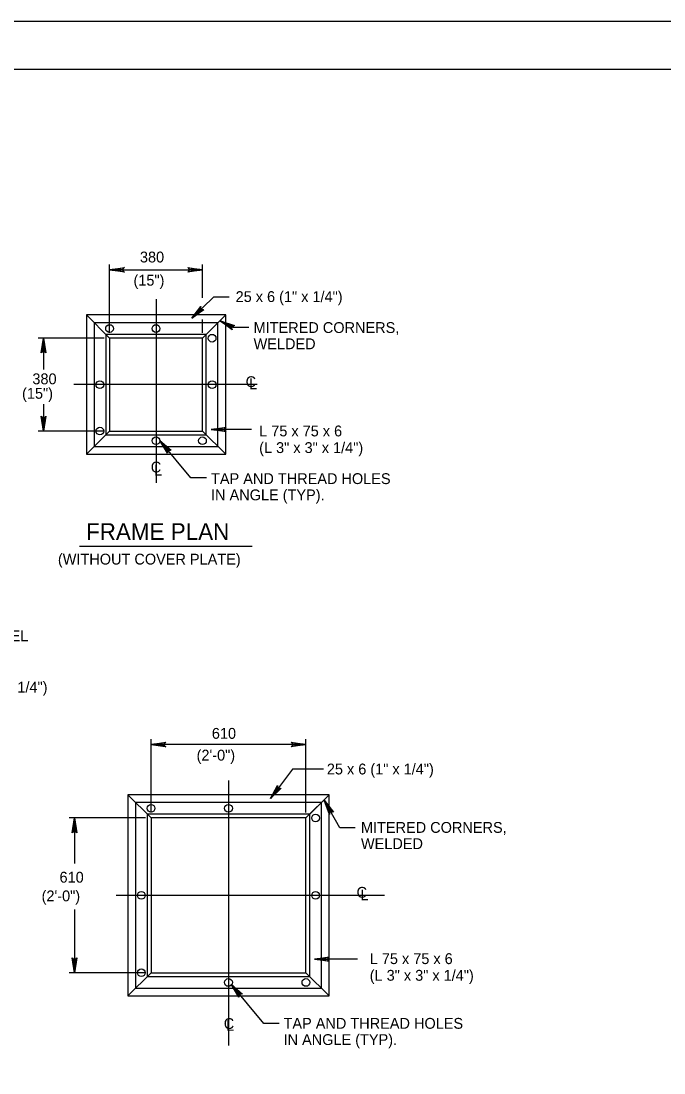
# Model space of a CAD drawing. Extents: x 638447 to 639352, y 298406 to 299000.
# Drawn here: x 638838.1 to 639037.5, y 298674.3 to 299000.5 of the extents above; entities that cross this region are included whole.
import ezdxf

# ---------------------------------------------------------------- set-up
doc = ezdxf.new("R2010")
doc.units = 0
for name, color, linetype in [('1', 7, 'Continuous'), ('2', 7, 'Continuous'), ('3', 7, 'Continuous'), ('PLT-BNDY', 7, 'Continuous')]:
    doc.layers.add(name, color=color, linetype=linetype)

msp = doc.modelspace()

# ---------------------------------------------------------------- linework, layer by layer
at = {"layer": '1'}
msp.add_lwpolyline([(639272.394625, 298421.4725), (639272.394625, 298985.4725), (638486.394625, 298985.4725), (638486.394625, 298421.4725), (639272.394625, 298421.4725), (639272.394625, 298447.8315), (639072.394625, 298447.8315), (639072.394625, 298512.509), (639272.394625, 298512.509), (639272.394625, 298541.4725), (639072.394625, 298541.4725), (639072.394625, 298421.4725), (639151.196125, 298421.4725), (639151.196125, 298447.8315), (639151.196125, 298421.4725), (639228.196125, 298421.4725), (639228.196125, 298447.8315), (639228.196125, 298435.515), (639272.394625, 298435.515)], dxfattribs=at)
at = {"layer": '2'}
for p, q in [((638865.586375, 298903.796), (638865.586375, 298925.002)), ((638894.386375, 298914.64725), (638894.386375, 298925.002)), ((638865.586375, 298923.322), (638894.386375, 298923.322)), ((638879.986375, 298914.196), (638879.986375, 298857.294)), ((638865.586375, 298902.116), (638858.386375, 298909.316)), ((638894.386375, 298902.116), (638901.586375, 298909.316)), ((638879.986375, 298905.116), (638879.986375, 298905.116)), ((638894.386375, 298903.796), (638894.386375, 298907.89375)), ((638863.906375, 298902.116), (638843.452375, 298902.116)), ((638845.132375, 298902.116), (638845.132375, 298892.43875)), ((638911.330375, 298887.716), (638854.500375, 298887.716)), ((638862.586375, 298887.716), (638862.586375, 298887.716)), ((638897.386375, 298887.716), (638897.386375, 298887.716)), ((638845.132375, 298881.65925), (638845.132375, 298873.316)), ((638863.906375, 298873.316), (638843.452375, 298873.316)), ((638858.386375, 298866.116), (638865.586375, 298873.316)), ((638901.586375, 298866.116), (638894.386375, 298873.316)), ((638879.986375, 298870.316), (638879.986375, 298870.316)), ((638878.458375, 298755.024), (638878.458375, 298777.77)), ((638926.458375, 298755.024), (638926.458375, 298777.77)), ((638926.458375, 298776.09), (638878.458375, 298776.09)), ((638902.458375, 298764.956), (638902.458375, 298682.822)), ((638878.458375, 298753.344), (638871.258375, 298760.544)), ((638926.458375, 298753.344), (638933.658375, 298760.544)), ((638927.658375, 298754.544), (638931.258375, 298758.144)), ((638876.778375, 298753.344), (638853.014375, 298753.344)), ((638854.694375, 298753.344), (638854.694375, 298739.25225)), ((638950.806375, 298729.344), (638867.594375, 298729.344)), ((638854.694375, 298724.96625), (638854.694375, 298705.344)), ((638876.778375, 298705.344), (638853.014375, 298705.344)), ((638871.258375, 298698.144), (638878.458375, 298705.344)), ((638933.658375, 298698.144), (638926.458375, 298705.344))]:
    msp.add_line(p, q, dxfattribs=at)
for points in [[(638869.944375, 298922.776), (638869.782375, 298923.092), (638865.586375, 298923.322), (638869.944375, 298922.776), (638870.168375, 298922.584), (638865.586375, 298923.322), (638869.780375, 298923.53), (638869.932375, 298923.842), (638865.586375, 298923.322), (638870.168375, 298924.052), (638869.932375, 298923.842)], [(638890.026375, 298923.87), (638890.190375, 298923.554), (638894.386375, 298923.322), (638890.026375, 298923.87), (638889.804375, 298924.062), (638894.386375, 298923.322), (638890.192375, 298923.116), (638890.040375, 298922.804), (638894.386375, 298923.322), (638889.804375, 298922.594), (638890.040375, 298922.804)], [(638902.660375, 298914.86), (638897.860375, 298914.86), (638891.046375, 298908.296)], [(638894.566375, 298910.926), (638894.230375, 298911.04), (638891.046375, 298908.296), (638894.566375, 298910.926), (638894.860375, 298910.944), (638891.046375, 298908.296), (638893.922375, 298911.354), (638893.816375, 298911.686), (638891.046375, 298908.296), (638893.842375, 298912), (638893.816375, 298911.686)], [(638858.386375, 298866.116), (638901.586375, 298866.116), (638901.586375, 298909.316), (638858.386375, 298909.316), (638858.386375, 298866.116)], [(638860.786375, 298868.516), (638899.186375, 298868.516), (638899.186375, 298906.916), (638860.786375, 298906.916), (638860.786375, 298868.516)], [(638908.720375, 298905.392), (638903.920375, 298905.392), (638899.884375, 298907.538)], [(638903.476375, 298905.008), (638903.480375, 298905.364), (638899.884375, 298907.538), (638903.476375, 298905.008), (638903.582375, 298904.736), (638899.884375, 298907.538), (638903.684375, 298905.754), (638903.964375, 298905.956), (638899.884375, 298907.538), (638904.272375, 298906.03), (638903.964375, 298905.956)], [(638844.584375, 298897.756), (638844.900375, 298897.918), (638845.132375, 298902.116), (638844.584375, 298897.756), (638844.392375, 298897.532), (638845.132375, 298902.116), (638845.338375, 298897.922), (638845.650375, 298897.768), (638845.132375, 298902.116), (638845.860375, 298897.532), (638845.650375, 298897.768)], [(638864.386375, 298872.116), (638895.586375, 298872.116), (638895.586375, 298903.316), (638864.386375, 298903.316), (638864.386375, 298872.116)], [(638865.586375, 298873.316), (638894.386375, 298873.316), (638894.386375, 298902.116), (638865.586375, 298902.116), (638865.586375, 298873.316)], [(638845.678375, 298877.674), (638845.362375, 298877.512), (638845.132375, 298873.316), (638845.678375, 298877.674), (638845.870375, 298877.898), (638845.132375, 298873.316), (638844.924375, 298877.508), (638844.612375, 298877.662), (638845.132375, 298873.316), (638844.402375, 298877.898), (638844.612375, 298877.662)], [(638901.466375, 298873.284), (638901.302375, 298873.6), (638897.106375, 298873.832), (638901.466375, 298873.284), (638901.688375, 298873.094), (638897.106375, 298873.832), (638901.300375, 298874.038), (638901.452375, 298874.352), (638897.106375, 298873.832), (638901.688375, 298874.56), (638901.452375, 298874.352)], [(638909.604375, 298873.832), (638904.804375, 298873.832), (638897.106375, 298873.832)], [(638895.592375, 298858.808), (638890.792375, 298858.808), (638881.200375, 298870.424)], [(638883.554375, 298866.714), (638883.694375, 298867.04), (638881.200375, 298870.424), (638883.554375, 298866.714), (638883.548375, 298866.42), (638881.200375, 298870.424), (638884.030375, 298867.322), (638884.368375, 298867.402), (638881.200375, 298870.424), (638884.680375, 298867.354), (638884.368375, 298867.402)], [(638882.818375, 298775.542), (638882.654375, 298775.858), (638878.458375, 298776.09), (638882.818375, 298775.542), (638883.040375, 298775.352), (638878.458375, 298776.09), (638882.652375, 298776.298), (638882.804375, 298776.61), (638878.458375, 298776.09), (638883.040375, 298776.818), (638882.804375, 298776.61)], [(638922.098375, 298776.638), (638922.262375, 298776.322), (638926.458375, 298776.09), (638922.098375, 298776.638), (638921.876375, 298776.828), (638926.458375, 298776.09), (638922.264375, 298775.882), (638922.112375, 298775.57), (638926.458375, 298776.09), (638921.876375, 298775.362), (638922.112375, 298775.57)], [(638931.898375, 298768.436), (638927.098375, 298768.436), (638922.298375, 298768.436), (638915.442375, 298759.352)], [(638918.504375, 298762.502), (638918.154375, 298762.562), (638915.442375, 298759.352), (638918.504375, 298762.502), (638918.792375, 298762.566), (638915.442375, 298759.352), (638917.802375, 298762.824), (638917.644375, 298763.136), (638915.442375, 298759.352), (638917.620375, 298763.45), (638917.644375, 298763.136)], [(638871.258375, 298698.144), (638933.658375, 298698.144), (638933.658375, 298760.544), (638871.258375, 298760.544), (638871.258375, 298698.144)], [(638873.658375, 298700.544), (638931.258375, 298700.544), (638931.258375, 298758.144), (638873.658375, 298758.144), (638873.658375, 298700.544)], [(638941.772375, 298750.268), (638936.972375, 298750.268), (638932.162375, 298758.826)], [(638933.820375, 298754.758), (638934.016375, 298755.054), (638932.162375, 298758.826), (638933.820375, 298754.758), (638933.762375, 298754.47), (638932.162375, 298758.826), (638934.396375, 298755.272), (638934.744375, 298755.292), (638932.162375, 298758.826), (638935.042375, 298755.188), (638934.744375, 298755.292)], [(638854.148375, 298748.984), (638854.464375, 298749.146), (638854.694375, 298753.344), (638854.148375, 298748.984), (638853.956375, 298748.76), (638854.694375, 298753.344), (638854.902375, 298749.15), (638855.214375, 298748.996), (638854.694375, 298753.344), (638855.422375, 298748.76), (638855.214375, 298748.996)], [(638877.258375, 298704.144), (638927.658375, 298704.144), (638927.658375, 298754.544), (638877.258375, 298754.544), (638877.258375, 298704.144)], [(638878.458375, 298705.344), (638926.458375, 298705.344), (638926.458375, 298753.344), (638878.458375, 298753.344), (638878.458375, 298705.344)], [(638855.242375, 298709.702), (638854.926375, 298709.54), (638854.694375, 298705.344), (638855.242375, 298709.702), (638855.434375, 298709.926), (638854.694375, 298705.344), (638854.488375, 298709.536), (638854.176375, 298709.69), (638854.694375, 298705.344), (638853.966375, 298709.926), (638854.176375, 298709.69)], [(638933.492375, 298709.04), (638933.330375, 298709.356), (638929.134375, 298709.588), (638933.492375, 298709.04), (638933.716375, 298708.85), (638929.134375, 298709.588), (638933.326375, 298709.796), (638933.480375, 298710.108), (638929.134375, 298709.588), (638933.716375, 298710.316), (638933.480375, 298710.108)], [(638942.461375, 298709.588), (638933.326375, 298709.588), (638929.134375, 298709.588)], [(638918.206375, 298689.576), (638913.406375, 298689.576), (638903.328375, 298701.82)], [(638905.676375, 298698.106), (638905.816375, 298698.432), (638903.328375, 298701.82), (638905.676375, 298698.106), (638905.670375, 298697.812), (638903.328375, 298701.82), (638906.154375, 298698.714), (638906.492375, 298698.794), (638903.328375, 298701.82), (638906.802375, 298698.744), (638906.492375, 298698.794)]]:
    msp.add_lwpolyline(points, dxfattribs=at)
for centre in [(638865.586181, 298905.115028), (638879.986181, 298905.115028), (638897.386181, 298902.115028), (638862.586181, 298887.715028), (638897.386181, 298887.715028), (638862.586181, 298873.315028), (638879.986181, 298870.315028), (638894.386181, 298870.315028), (638878.458341, 298756.343348), (638902.458341, 298756.343348), (638929.458341, 298753.343348), (638875.458341, 298729.343348), (638929.458341, 298729.343348), (638875.458341, 298705.343348), (638902.458341, 298702.343348), (638926.458341, 298702.343348)]:
    msp.add_circle(centre, 1.2, dxfattribs=at)
at = {"layer": '3'}
msp.add_line((638856.275875, 298837.62), (638909.845875, 298837.62), dxfattribs=at)
at = {"layer": 'PLT-BNDY'}
msp.add_lwpolyline([(638447.394625, 299000.4725), (639288.394625, 299000.4725), (639288.394625, 298406.4725), (638447.394625, 298406.4725)], close=True, dxfattribs=at)

# ---------------------------------------------------------------- texts
at = {"layer": '1'}
for s, p in [('(15")', (638873.008375, 298918.41425)), ('(15")', (638838.461875, 298883.34825)), ('(27 5/8" x 27 5/8" x 1/4")', (638797.850885, 298792.2405)), ('(2\'-0")', (638892.570375, 298771.13625)), ('(2\'-0")', (638844.516875, 298727.49875))]:
    msp.add_text(s, height=3.36, dxfattribs=at).set_placement(p)
at = {"layer": '3'}
for s, height, p in [('380', 3.36, (638875.010625, 298925.61)), ('25 x 6 (1" x 1/4")', 3.36, (638904.673027, 298913.34)), ('MITERED CORNERS,', 3.359988, (638910.244375, 298903.738)), ('WELDED', 3.359988, (638910.244375, 298898.698)), ('380', 3.36, (638841.662625, 298887.8385)), ('C', 3.359988, (638907.776375, 298886.954)), ('L', 3.359988, (638908.822375, 298886.306)), ('L 75 x 75 x 6', 3.36, (638911.967625, 298871.673)), ('(L 3" x 3" x 1/4")', 3.36, (638911.967625, 298866.513)), ('C', 3.359988, (638878.360375, 298860.476)), ('L', 3.359988, (638879.360375, 298859.506)), ('TAP AND THREAD HOLES', 3.359988, (638897.050375, 298856.892)), ('IN ANGLE (TYP).', 3.359988, (638897.050375, 298851.852)), ('FRAME PLAN', 5.2000005, (638858.282875, 298839.55)), ('(WITHOUT COVER PLATE)', 3.359988, (638849.574375, 298831.928)), ('CHECKERED STEEL', 3.359988, (638796.707125, 298808.15175)), ('610', 3.36, (638897.306125, 298777.897)), ('25 x 6 (1" x 1/4")', 3.36, (638932.95519, 298766.8425)), ('MITERED CORNERS,', 3.359988, (638943.530375, 298748.73)), ('WELDED', 3.359988, (638943.530375, 298743.69)), ('610', 3.36, (638850.076625, 298733.292)), ('C', 3.359988, (638942.166375, 298728.604)), ('L', 3.359988, (638943.350375, 298727.802)), ('L 75 x 75 x 6', 3.36, (638946.254375, 298708.032)), ('(L 3" x 3" x 1/4")', 3.36, (638946.254375, 298702.872)), ('C', 3.359988, (638900.988375, 298687.908)), ('L', 3.359988, (638901.750375, 298687.348)), ('TAP AND THREAD HOLES', 3.359988, (638919.528375, 298687.976)), ('IN ANGLE (TYP).', 3.359988, (638919.528375, 298682.936))]:
    msp.add_text(s, height=height, dxfattribs=at).set_placement(p)

doc.saveas('drawing.dxf')
